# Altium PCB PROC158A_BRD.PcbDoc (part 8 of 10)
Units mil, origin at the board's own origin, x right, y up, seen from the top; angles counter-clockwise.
Board outline 3346.45 x 4921.26 mil, 8 copper layers (Top Layer, GND1, SIG1, PWR1, PWR2, SIG2, GND2, Bottom Layer), stack 54.534 mil thick; 718 components, 459 nets, 2307 pads, 1179 vias.
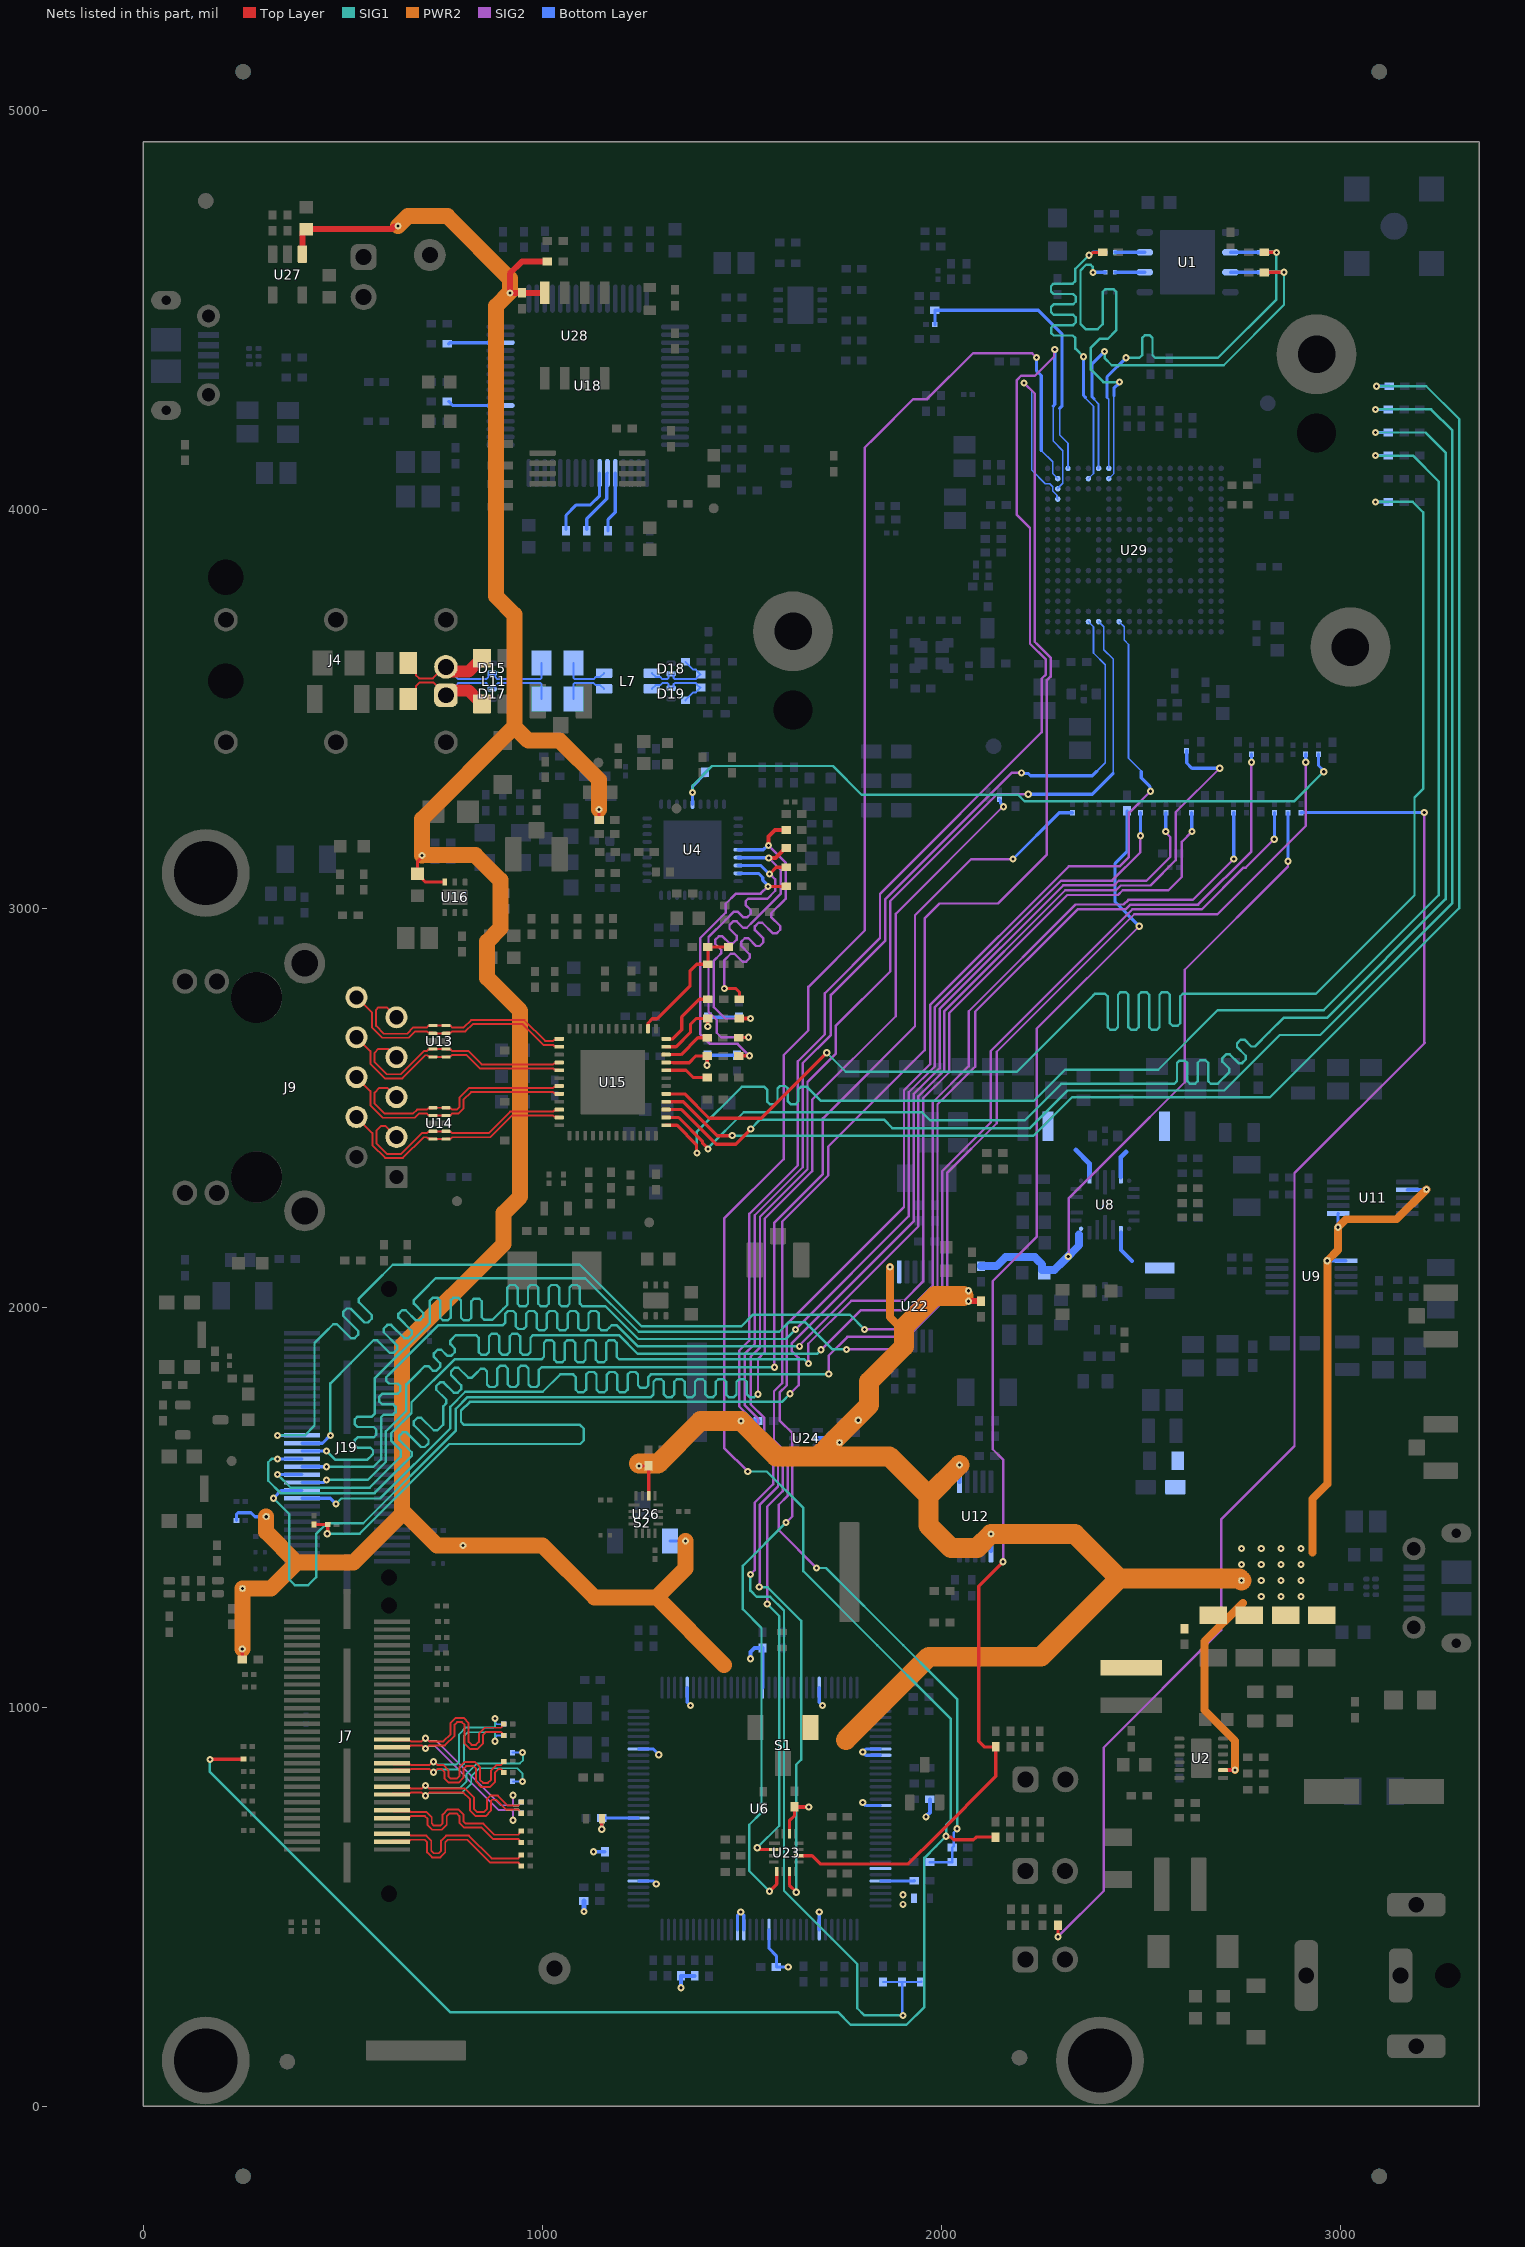
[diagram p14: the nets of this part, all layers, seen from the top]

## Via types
v1: diameter 18, hole 8, Top Layer to Bottom Layer, tented both sides, 1112 vias
v2: diameter 19.68, hole 7.87, Top Layer to Bottom Layer, 28 vias
v3: diameter 20, hole 10, Top Layer to Bottom Layer, tented both sides, 26 vias
v4: diameter 16/18/18/18/18/18/18/16 (per signal layer), hole 8, Top Layer to Bottom Layer, tented both sides, 13 vias

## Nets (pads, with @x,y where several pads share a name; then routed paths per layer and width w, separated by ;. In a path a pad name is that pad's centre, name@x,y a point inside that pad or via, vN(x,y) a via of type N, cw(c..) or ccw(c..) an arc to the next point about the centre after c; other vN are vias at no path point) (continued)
QSPI_D1: R39.1 R49.1 U29.U7 | length 1001.3
  Top Layer w8: R49.1@2808.26,4644.33 2808.36,4644.23 2838.37,4644.23 v1(2838.46,4644.14)
  SIG1 w6: v1(2462,4380) 2492.6,4380 2495.6,4380 2502.1,4386.5 2502.1,4429.71 2508.6,4436.21 2521.6,4436.21 2528.1,4429.71 2528.1,4386.5 2534.6,4380 2570,4380 2692,4380 2838.46,4526.46 v1(2838.46,4644.14)
  Bottom Layer w4: 2414.36,4281 2418.84,4276.52 U29.U7@2418.84,4102.97
  Bottom Layer w6.42: 2414.26,4281.11 2414.26,4282.37
  Bottom Layer w8: 2414.26,4281.11 2414.36,4281 ; 2414.26,4282.37 2414.26,4332.26 v1(2462,4380) ; R39.1@2818.26,4644.33 2818.36,4644.23 2838.37,4644.23 v1(2838.46,4644.14)
QSPI_D1_FLASH: R39.2 U1.2 | length 71.2
  Bottom Layer w8: U1.2@2723.49,4644.33 R39.2@2794.64,4644.33
QSPI_D2: R42.1 R43.1 U29.U6 | length 1020.6
  Top Layer w8: R43.1@2808.26,4594.03 2808.44,4594.21 2857.53,4594.21 v1(2857.71,4594.38)
  SIG1 w6: v1(2408.22,4396.17) 2408.22,4379.49 2426.19,4361.51 2706.51,4361.51 2857.71,4512.71 v1(2857.71,4594.38)
  Bottom Layer w4.5: 2381.66,4277.63 2381.66,4275.73 2393.25,4264.14 2393.25,4134.47 U29.U6@2393.25,4102.97
  Bottom Layer w8: 2381.66,4277.63 2376.29,4283.01 2376.29,4364.24 v1(2408.22,4396.17) ; R42.1@2818.26,4594.03 2818.44,4594.21 2857.53,4594.21 v1(2857.71,4594.38)
QSPI_D2_FLASH: R42.2 U1.3 | length 71.3
  Bottom Layer w8: U1.3@2723.49,4594.33 2723.64,4594.18 2794.49,4594.18 R42.2@2794.64,4594.03
QSPI_D3: R40.2 R41.1 U29.T5 | length 1004.9
  Top Layer w8: v1(2369,4637) 2371.71,4637 2378.87,4644.17 2403.24,4644.17 R41.1@2403.41,4644.33
  SIG1 w6: v1(2355.3,4382.67) 2335,4402.97 2335,4426.39 2335,4429.39 2328.5,4435.89 2280.76,4435.89 2274.26,4442.39 2274.26,4455.39 2280.76,4461.89 2329.28,4461.89 2335.78,4468.39 2335.78,4481.39 2329.28,4487.89 2280.48,4487.89 2273.98,4494.39 2273.98,4507.39 2280.48,4513.89 2329.28,4513.89 2335.78,4520.39 2335.78,4533.39 2329.28,4539.89 2280.48,4539.89 2273.98,4546.39 2273.98,4559.39 2280.48,4565.89 2328.5,4565.89 2335,4572.39 2335,4600.06 2335,4603 v1(2369,4637)
  Bottom Layer w4: 2359.99,4280.69 2359.99,4279.08 2380.42,4258.64 2380.42,4090.14 U29.T5@2367.66,4077.38
  Bottom Layer w8: v1(2355.3,4382.67) 2355.3,4285.69 2359.99,4281 ; v1@2369,4634.29 v1(2369,4637) 2371.71,4637 2379.04,4644.33 R40.2@2410.27,4644.33
QSPI_D3_FLASH: R40.1 U1.7 | length 74.9
  Bottom Layer w8: R40.1@2433.89,4644.33 U1.7@2508.8,4644.33
QSPI_SCLK: R44.2 U29.T7 | length 975.4
  SIG1 w6: v1(2379,4594) 2378.77,4594.23 2378.77,4607.23 2373.08,4612.92 2361.89,4612.92 2347.78,4598.81 2347.78,4464.52 2360.38,4451.92 2391.23,4451.92 2403.57,4464.26 2403.57,4545.33 2410.27,4552.02 2430.36,4552.02 2437,4545.38 2437,4448.44 2416,4427.44 2395.47,4427.44 2373.82,4405.79 2373.82,4350.49 2405.1,4319.21 v1(2445.85,4319.21)
  Bottom Layer w4: U29.T7@2418.84,4077.38 2431.6,4090.14 2431.6,4284.99
  Bottom Layer w8: v1(2379,4594) 2379.17,4594.17 2410.11,4594.17 R44.2@2410.27,4594.33 ; 2431.6,4284.99 2431.6,4303.76 2445.85,4318.01 v1(2445.85,4319.21)
QSPI_SCLK_FLASH: R44.1 U1.6 | length 74.9
  Bottom Layer w8: R44.1@2433.89,4594.33 U1.6@2508.8,4594.33
REF_FTDI: R157.2 U18.6 | length 134.4
  Bottom Layer w8: R157.2@765.07,4270.79 775.38,4260.47 U18.6@895.17,4260.47
REGOUT_3V3: C18.2 C22.2 C23.1 C25.1 C26.1 C29.1 C41.1 C42.2 C43.2 C47.2 C48.1 C50.1 C61.1 C76.2 C98.2 C133.1 C145.1 L1.1 L6.2 R11.1 R50.2 R124.2 R127.2 R134.2 R140.2 R155.2 R199.1 R200.1 R222.2 R243.2 R317.1 R416.2 R418.2 R503.1 R508.1 S1.1 S2.1 U2.8 U6.7 U6.8 U6.16 U6.26 U6.28 U6.39 U6.47 U6.51 U6.52 U6.69 U6.79 U6.90 U6.101 U6.113 U6.122 U9.6 U11.2 U11.6 U12.1 U12.6 U16.6 U22.6 U23.14 U24.5 U26.14 U27.1 U28.8 | length 14027.4
  Top Layer w8: v1(248.03,1145.67) 248.18,1145.52 248.18,1119.7 R418.2@248.33,1119.56 ; C48.1@687.02,3091.34 687.02,3118.92 698.58,3130.48 v1(698.58,3133.19) ; C48.1@688.62,3086.79 698.46,3076.95 698.46,3075.35 707.08,3066.73 U16.6@754.99,3066.73 ; v1(1141.69,3248.21) 1141.88,3248.03 1141.88,3222.47 R50.2@1142.06,3222.28 ; v1(1148.38,693.81) 1148.69,694.13 1148.69,720.31 C61.1@1149.01,720.62 ; v1(1242,1604) C18.2@1266.05,1604.02 1266.12,1603.95 1266.12,1529.74 U26.14@1266.18,1529.68 ; U23.14@1618.56,682.49 1618.56,715.04 1631.35,727.84 C98.2@1631.35,749.83
  Top Layer w10: C98.2@1631.35,749.83 v1(1667,749.83) ; U2.8@2705.09,842 v1(2735,842)
  Top Layer w15: U27.1@398.76,4642.54 398.76,4693.57 407.46,4702.27 C145.1@408.44,4702.27 621.36,4702.27 628.52,4709.43 637.43,4709.43 v1(638,4710) ; U28.8@1005.83,4543.13 1005.29,4542.59 C47.2@949.01,4542.59 v1(918.52,4542.59) 918.52,4591.26 948.21,4620.96 R416.2@1012.52,4620.96 ; v1(2066.93,2016.81) R199.1@2099,2016.81
  PWR2 w20: v1(1870.3,2102.69) 1870.3,1976.6 1894.95,1951.95 1905.95,1951.95 ; v1(2735,842) 2735,915.5 2658,992.5 2658,1164 2755,1261 ; 2928.91,1387 2928.91,1521.63 2966.18,1558.9 v1(2966.18,2118.23) 2993,2145.06 v1(2993,2201.81) 3013.19,2222 3139.65,2222 v1(3214.34,2296.69)
  PWR2 w40: v1(248.03,1145.67) 248.33,1145.97 v1(248.33,1297.35) 320.57,1297.35 385.03,1361.81 ; v1(308,1477) 308,1438.84 385.03,1361.81 ; v1(638,4710) 662.86,4734.86 762.14,4734.86 918.52,4578.48 918.52,4544.24 883.71,4509.43 883.71,3782.69 929.78,3736.61 929.78,3455.89 ; v1(1141.69,3248.21) 1141.69,3322.76 1043.3,3421.16 964.52,3421.16 929.78,3455.89 ; v1(1358,1416.13) 1358,1346.93 1285.85,1274.77 ; 1454.69,1105.93 1285.85,1274.77 ; 385.03,1361.81 526.09,1361.81 647.72,1483.44 647.72,1492.6 ; 647.72,1492.6 647.72,1905.23 902.57,2160.08 902.57,2237.49 943.9,2278.81 943.9,2744.1 861.26,2826.74 861.26,2917.6 894.66,2951.01 894.66,3071.34 832,3134 699.4,3134 v1(698.58,3133.19) 698.58,3224.69 929.78,3455.89 ; 647.72,1492.6 735.32,1405 v1(801,1405) 801.09,1405.09 1000,1405.09 1130.32,1274.77 1285.85,1274.77
  PWR2 w50: v1@1242,1609.85 1289.23,1609.85 1395.85,1716.46 v1(1497.18,1716.46) 1585.41,1628.24 1690.24,1628.24 ; 1760,918 1968,1126 2248.64,1126 2444.82,1322.18 ; v1(2044.72,1606.52) 1967.6,1529.4 ; 2054.22,2029.52 1983.52,2029.52 1905.95,1951.95 1905.95,1903 1818.5,1815.56 1818.5,1756.5 1690.24,1628.24 ; v1(2750.82,1317.28) 2745.92,1322.18 2444.82,1322.18 ; 1690.24,1628.24 1868.76,1628.24 1967.6,1529.4 ; 1967.6,1529.4 1967.6,1454.4 2023,1399 2089.17,1399 v1(2123.47,1433.29) 2333.71,1433.29 2444.82,1322.18
  Bottom Layer w8: R508.1@233.42,1467.61 233.42,1482.31 238.11,1487 270,1487 280,1477 v1(308,1477) ; v1(1128,637.67) R155.2@1156.34,637.67 ; v1(1141.69,3248.21) 1141.88,3248.03 1141.88,3222.47 R11.1@1142.06,3222.28 ; v1(1148.38,693.81) C42.2@1148.38,722.02 ; C42.2@1148.63,721.77 U6.79@1240.63,721.77 ; U6.69@1240.63,564.29 1277.34,564.29 v1(1285.22,556.42) ; U6.90@1240.63,895 1277.34,895 1291.55,880.79 v1(1291.55,880.41) ; S2.1@1319.33,1416.13 v1(1358,1416.13) ; U6.101@1362.68,1048.54 1362.68,1011.83 v1(1370.55,1003.96) ; U6.52@1488.66,442.24 1488.66,478.96 v1(1496.54,486.83) 1504.41,478.96 U6.51@1504.41,442.24 ; U6.113@1551.66,1048.54 C43.2@1551.66,1147.93 ; U6.47@1567.4,442.24 1567.4,395.41 1586.14,376.67 C50.1@1586.14,349.16 v1(1615.94,349.16) ; U6.39@1693.39,442.24 v1(1693.39,486.83) ; U6.122@1693.39,1048.54 1693.39,1011.83 v1(1701.26,1003.96) ; v1(1802.35,761.14) 1810.22,753.27 U6.16@1846.93,753.27 ; U6.28@1846.93,564.29 1847,564.35 1930.8,564.35 C76.2@1931.26,564.81 ; U6.8@1846.93,879.25 1810.22,879.25 v1(1802.35,887.13) 1810.22,895 U6.7@1846.93,895 ; v1(2966.18,2118.23) U9.6@3013.19,2118.23 ; v1(2993,2201.81) 2993,2236.16 U11.6@2993.39,2236.54 ; U11.2@3166.61,2295.6 3167.16,2296.14 3213.79,2296.14 v1(3214.34,2296.69)
  Bottom Layer w10: v1(248.33,1297.35) R503.1@278.9,1297.35 ; R243.2@753.28,1405.09 753.33,1405.05 800.95,1405.05 v1(801,1405) ; v1(1346.93,297) R124.2@1346.93,326.49 R127.2@1381.51,326.49 ; v1(1521,1121) 1521,1137.5 1531.43,1147.93 C43.2@1551.66,1147.93 ; v1(1961,725) 1961,727.16 1970.26,736.43 R140.2@1970.26,769.02 ; U12.6@2044.72,1564.42 v1(2044.72,1606.52) ; U12.1@2123.47,1391.19 v1(2123.47,1433.29)
  Bottom Layer w12: R134.2@1103.84,513.97 1104,513.81 v1(1104,488) ; v1@1497.18,1715.94 1497.71,1716.46 R222.2@1540.02,1716.46 ; U24.5@1689.61,1673.65 1709.42,1673.65 1721.27,1685.5 1743.75,1685.5 C133.1@1744.05,1685.81 v1(1744.05,1662.87) ; R317.1@1766.1,1718.43 1766.17,1718.5 1791.01,1718.5 v1(1791.08,1718.57)
  other v1: 1903,505.81 1903,529.81 2800.62,1277.28 2850.42,1277.28 2900.22,1277.28 2800.62,1317.28 2850.42,1317.28 2900.22,1317.28 2750.82,1357.28 2800.62,1357.28 2850.42,1357.28 2900.22,1357.28 2750.82,1397.28 2800.62,1397.28 2850.42,1397.28 2900.22,1397.28 2066.93,2043
RGMII_RD0: R173.1 R287.2 R325.2 U15.33 | length 232.9
  Top Layer w8: U15.33@1309.79,2614.76 1327.42,2614.76 ; 1327.89,2614.28 1367.54,2614.28 1384.57,2631.31 R325.2@1413.34,2631.31 1412.77,2630.74 1412.77,2608.54 v1(1412.19,2607.97)
  Bottom Layer w8: v1(1412.19,2607.97) 1412.7,2608.48 1412.7,2632.17 R173.1@1413.21,2632.68 R287.2@1487,2632.68
RGMII_RD1: R336.2 U15.34 | length 120.3
  Top Layer w8: U15.34@1309.79,2634.44 1347.28,2634.46 1389.42,2676.6 R336.2@1412.62,2676.6
RGMII_RD2: R286.1 R288.2 R338.2 U15.35 | length 267.5
  Top Layer w8: U15.35@1309.79,2654.13 1309.83,2654.16 1334.89,2654.16 1370.98,2690.25 1370.98,2710.51 1385.35,2724.89 R338.2@1414.06,2724.89 ; v1(1414.1,2704.62) R338.2@1414.08,2724.87
  Bottom Layer w8: v1(1414.1,2704.62) 1414.29,2704.81 1414.29,2727.67 R286.1@1414.48,2727.86 R288.2@1492.8,2727.86
RGMII_RD3: R339.2 U15.36 | length 164.6
  Top Layer w8: U15.36@1309.79,2673.81 1326.17,2673.81 1348.89,2696.53 1348.89,2728.82 1393.09,2773.01 1414.25,2773.01 R339.2@1414.33,2773.09
RGMII_TCLK: R98.2 U15.29 | length 3965.6
  Top Layer w8: U15.29@1309.79,2536.01 1356.25,2536.01 1417.23,2475.04 1548.04,2475.04 v1(1712,2639)
  SIG1 w6: v1(1712,2639) 1759.62,2591.38 2188.38,2591.38 2380.24,2783.24 2384,2787 2409.24,2787 2415.74,2780.5 2415.74,2703.25 2422.24,2696.75 2435.24,2696.75 2441.74,2703.25 2441.74,2784.4 2448.24,2790.9 2461.24,2790.9 2467.74,2784.4 2467.74,2703.25 2474.24,2696.75 2487.24,2696.75 2493.74,2703.25 2493.74,2784.4 2500.24,2790.9 2513.24,2790.9 2519.74,2784.4 2519.74,2703.25 2526.24,2696.75 2539.24,2696.75 2545.74,2703.25 2545.74,2784.4 2552.24,2790.9 2565.24,2790.9 2571.74,2784.4 2571.74,2713.18 2578.24,2706.68 2591.24,2706.68 2597.74,2713.18 2597.74,2780.5 2604.24,2787 2644.31,2787 2937.71,2787 3184.5,3033.79 3184.5,3278.5 3206,3300 3206,3993 3180,4019 v1(3087,4019)
  Bottom Layer w8: v1(3087,4019) R98.2@3119.26,4019
RGMII_TD0: R103.2 U15.28 | length 3757.7
  Top Layer w8: U15.28@1309.79,2516.33 1352.78,2516.33 1438.11,2431 1475.18,2431 v1(1475.64,2431.46)
  SIG1 w6: v1(1475.64,2431.46) 1476.1,2431 2229.96,2431 2326.46,2527.5 2822.62,2527.5 3296.45,3001.33 3296.45,4226.55 3214.16,4308.84 v1(3088.97,4308.84)
  Bottom Layer w8: v1(3088.97,4308.84) R103.2@3121.23,4308.84
RGMII_TD1: R105.2 U15.27 | length 3703.7
  Top Layer w8: U15.27@1309.79,2496.64 1348.5,2496.64 1435.14,2410 1484.5,2410 1521.98,2447.48 v1(1521.98,2448.18)
  SIG1 w6: v1(1521.98,2448.18) 1545.3,2471.5 1855.23,2471.5 1876.31,2450.43 2220.92,2450.43 2315,2544.5 2708.06,2544.5 2847.1,2683.54 2948.54,2683.54 3279.45,3014.45 3279.45,3164.43 3279.45,4197.55 3226.13,4250.87 v1(3087,4250.87)
  Bottom Layer w8: v1(3087,4250.87) R105.2@3119.26,4250.87
RGMII_TD2: R121.2 U15.26 | length 3948.5
  Top Layer w8: U15.26@1309.79,2476.96 1341.07,2476.96 1400.67,2417.36 1400.67,2413.37 1415,2399.05 v1(1415,2398)
  SIG1 w6: v1(1415,2398) 1415,2400.7 1504.44,2490.13 1951.12,2490.13 1971.25,2470 2208.5,2470 2300,2561.5 2579.97,2561.5 2582.97,2561.5 2589.47,2568 2589.47,2613.06 2595.97,2619.56 2608.97,2619.56 2615.47,2613.06 2615.47,2568 2621.97,2561.5 2634.97,2561.5 2641.47,2568 2641.47,2613.97 2647.97,2620.47 2660.97,2620.47 2667.47,2613.97 2667.47,2568 2673.97,2561.5 2691.33,2561.5 2692.74,2562.91 2718.18,2588.34 2720.3,2590.47 2720.3,2599.66 2703.21,2616.74 2703.21,2625.94 2712.4,2635.13 2721.6,2635.13 2743.53,2613.2 2752.72,2613.2 2761.91,2622.39 2761.91,2631.58 2739.98,2653.51 2739.98,2662.71 2749.17,2671.9 2758.37,2671.9 2775.45,2654.81 2784.64,2654.81 2820.59,2690.76 2856.33,2726.5 2965,2726.5 3262.45,3023.95 3262.45,4142.55 3212.09,4192.91 v1(3087,4192.91)
  Bottom Layer w8: v1(3087,4192.91) R121.2@3119.26,4192.91
RGMII_TD3: R122.2 U15.25 | length 3704.5
  Top Layer w8: U15.25@1309.79,2457.27 1337.4,2457.27 1385.67,2409 1385.67,2389.33 v1(1387,2388)
  SIG1 w6: v1(1387,2388) 1387,2441.5 1499.18,2553.68 1527.34,2553.68 1556.34,2553.68 1562.84,2547.18 1562.84,2516.94 1569.34,2510.44 1582.34,2510.44 1588.84,2516.94 1588.84,2549.44 1595.34,2555.94 1608.34,2555.94 1614.84,2549.44 1614.84,2516.94 1621.34,2510.44 1634.34,2510.44 1640.84,2516.94 1640.84,2547.18 1647.34,2553.68 1657.13,2553.68 1662.92,2553.68 1698.1,2518.5 2230.9,2518.5 2309.11,2596.71 2542.57,2596.71 2691.37,2745.5 2957,2745.5 3245.45,3033.95 3245.45,4069.87 3180.39,4134.94 v1(3087,4134.94)
  Bottom Layer w8: v1(3087,4134.94) R122.2@3119.26,4134.94
RST_FTDI: R163.2 U18.14 | length 131.3
  Bottom Layer w8: R163.2@765.07,4415.03 767.99,4417.95 U18.14@895.17,4417.95
RX_CLK: R290.2 U15.32 | length 110.7
  Top Layer w8: U15.32@1309.79,2595.07 1359.53,2595.07 1377.58,2577.02 R290.2@1413.04,2577.02
RX_CTRL: R195.2 R211.1 R289.2 U15.38 | length 341.8
  Top Layer w8: U15.38@1264.51,2699.4 1264.51,2713.47 1275.25,2724.21 1287.3,2724.21 1324.95,2761.86 1324.95,2762.1 1369.9,2807.06 1369.9,2844.66 1386.05,2860.81 R195.2@1414.32,2860.81 R211.1@1414.33,2903.81 R289.2@1466,2903.81
RX_D0: R237.2 R255.1 U4.26 | length 784.6
  Top Layer w8: R237.2@1492.08,2631.31 1492.14,2631.37 v1(1518.69,2631.37) ; v1(1564.68,3055.84) 1564.79,3055.95 1606.29,3055.95 R255.1@1606.4,3056.06
  SIG2 w6: v1(1518.69,2631.37) 1488.85,2661.21 1419.56,2661.21 1394.93,2685.84 1394.93,2925.75 1459.31,2990.13 1459.31,3012.41 1484.52,3037.62 1546.46,3037.62 v1(1564.68,3055.84)
  Bottom Layer w8: U4.26@1490.38,3088.51 1541.28,3088.51 1551.71,3078.07 1551.71,3071.5 1564.68,3058.54 v1(1564.68,3055.84)
RX_D1: R238.2 R256.1 U4.25 | length 802.1
  Top Layer w8: R238.2@1491.36,2676.6 1491.97,2677.21 1515.39,2677.21 v1(1516,2677.81) ; v1(1568.7,3086.55) 1586.1,3103.94 R256.1@1606.4,3103.94
  SIG2 w6: v1(1516,2677.81) 1447.69,2677.81 1436.43,2689.07 1436.43,2721.14 1415.97,2741.61 1415.97,2928.84 1459.18,2972.05 1479.69,2992.55 1488.88,2992.55 1503.38,2978.06 1512.57,2978.06 1521.76,2987.25 1521.76,2996.44 1508.83,3009.37 1508.83,3018.56 1515.33,3025.06 1520.54,3025.06 1563.37,3025.06 1583.15,3044.83 1583.15,3073.31 1569.91,3086.55 v1(1568.7,3086.55)
  Bottom Layer w8: U4.25@1490.38,3108.2 1547.05,3108.2 v1(1568.7,3086.55)
RX_D2: R239.2 R257.1 U4.24 | length 833.2
  Top Layer w10: R239.2@1492.8,2724.89 1492.84,2724.85 1520.96,2724.85 v1(1521,2724.81) ; v1(1566.7,3126.89) 1583.29,3126.89 1608.37,3151.97 R257.1@1610.34,3151.97
  SIG2 w6: v1(1521,2724.81) 1457.75,2724.81 1429.58,2752.98 1429.58,2870.08 1445.47,2885.96 1447.59,2888.08 1447.59,2897.28 1432.57,2912.3 1432.57,2921.49 1441.76,2930.69 1450.95,2930.69 1468.22,2913.42 1477.41,2913.42 1486.6,2922.61 1486.6,2931.8 1468.53,2949.88 1468.53,2959.07 1477.72,2968.26 1486.91,2968.26 1502.74,2952.43 1511.94,2952.43 1528.41,2968.9 1597.18,3037.67 1597.18,3096.41 v1(1566.7,3126.89)
  Bottom Layer w8: U4.24@1490.38,3127.88 1490.87,3127.39 1566.21,3127.39 v1(1566.7,3126.89)
RX_D3: R16.1 R240.2 U4.23 | length 871.1
  Top Layer w8: v1(1455.65,2800.13) 1484.49,2800.13 1493.56,2791.05 R240.2@1493.56,2773.59
  Top Layer w10: v1(1566.5,3158.03) 1566.5,3180.27 1583.04,3196.81 R16.1@1610.34,3196.81
  SIG2 w6: v1(1455.65,2800.13) 1455.65,2862.32 1455.65,2871.28 1471.67,2887.31 1480.86,2887.31 1501.02,2867.15 1510.21,2867.15 1519.4,2876.34 1519.4,2885.54 1497.55,2907.39 1497.55,2916.58 1506.74,2925.78 1515.94,2925.78 1535.11,2906.6 1544.31,2906.6 1553.5,2915.79 1553.5,2924.98 1532.07,2946.41 1532.07,2955.6 1541.27,2964.79 1550.46,2964.79 1577.26,2937.99 1586.45,2937.99 1595.65,2947.18 1595.65,2956.37 1572.79,2979.23 1572.79,2988.42 1604.97,3020.61 1609.18,3024.82 1609.18,3115.35 v1(1566.5,3158.03)
  Bottom Layer w8: U4.23@1490.38,3147.57 1553.42,3147.57 1563.88,3158.03 v1(1566.5,3158.03)
SOP0_FTDI: R171.1 U18.55 | length 196.5
  Bottom Layer w8: R171.1@1058.91,3950.19 1058.91,3985.34 1085.16,4011.58 1120.24,4011.58 1143.2,4034.54 U18.55@1143.2,4091.18
SOP0_TDO: R310.1 R386.1 U23.10 | length 3271.9
  Top Layer w8: U23.10@1642.18,627.37 1675.44,627.37 1695.81,607 1916.35,607 1986,676.65 2135.56,826.21 R310.1@2135.56,900.17 2106.83,900.17 2092.72,914.28 2092.72,1302.72 v1(2154,1364)
  SIG2 w6: v1(2154,1364) 2154,1619.76 2128,1645.76 2128,2067.46 2238,2177.46 2238,2699.1 v1(2495.08,2956.18)
  Bottom Layer w8: R386.1@2464,3245.02 2464.5,3244.52 2464.5,3143.5 2434.5,3113.5 2434.5,3016.75 v1(2495.08,2956.18)
SOP1_FTDI: R170.1 U18.54 | length 162.4
  Bottom Layer w8: R170.1@1111.12,3950.19 1111.12,3976.45 1161.12,4026.45 1161.12,4089.42 U18.54@1162.89,4091.18
SOP1_MSS_SPIB_CS2: R305.1 R324.1 U29.T2 | length 7516.5
  Top Layer w8: v1(167,869) 167.41,869.41 250.57,869.41 R324.1@250.98,869.81 ; v1(2011.22,676.41) 2013.13,674.5 2023.01,674.5 2029.7,667.81 2079.81,667.81 2086.32,674.32 2133.84,674.32 R305.1@2134.62,673.54
  SIG1 w6: v1(167,869) 167,837.46 768.64,235.81 1740.26,235.81 1772.07,204 1911.93,204 1956.87,248.94 1956.87,271 1956.87,622.06 1986,651.19 v1(2011.22,676.41) 2011.22,704.65 2022.51,715.95 2022.51,971.28 1986,1007.8 1838.8,1155 1653.52,1340.28 1653.52,1498.48 1562,1590 v1(1514.49,1590)
  SIG2 w6: v1(1514.49,1590) 1455.18,1649.31 1455.18,2223.5 1604,2372.32 1604,2632.99 1666.33,2695.32 1666.33,2804.24 1807.5,2945.41 1807.5,4155 1834.5,4182 ; 1834.52,4181.98 1929,4276.46 1963.66,4276.46 2078.67,4391.47 2226.62,4391.47 v1(2237.29,4380.8)
  Bottom Layer w4: 2249.81,4147.65 2278.05,4119.41 2278.05,4108.27 ; 2278.05,4097.67 2278.05,4090.23 U29.T2@2290.89,4077.38 ; 2278.06,4097.69 2278.06,4108.26
  Bottom Layer w8: v1(2237.29,4380.8) 2237.29,4347.92 2249.48,4335.73 2249.48,4147.98 2249.81,4147.65
SOP2_FTDI: R169.1 U18.53 | length 152.4
  Bottom Layer w8: R169.1@1164.49,3946.25 1164.49,3975.2 1182.57,3993.28 U18.53@1182.57,4091.18
SOP2_PMIC_CLK: R218.2 R299.1 | length 3537
  Top Layer w8: v1(2291.63,424.85) R299.1@2291.63,453.72
  SIG2 w6: v1(2291.63,424.85) 2406,539.22 2406,898.6 2700.13,1192.74 2700.13,1469.71 2884,1653.58 2884,2337.58 3210.5,2664.08 3209.07,2665.51 v1(3209.07,3240.92)
  Bottom Layer w8: R218.2@2899.94,3240.92 v1(3209.07,3240.92) 3209.8,3240.92 v1@3210.16,3240.56 ; R218.2@2900.69,3240.22 R218.2@2901.03,3240.56
SOP3_MSS_UARTB_TX: R136.1 R301.1 R303.2 U29.P2 | length 4721.6
  SIG1 w6: v1(1686.77,1348.39) 1710.5,1348.39 1903.89,1155 1986,1072.89 2038.8,1020.09 v1(2038.8,694.99)
  SIG2 w6: v1(1686.77,1348.39) 1592,1443.16 1592,1506.97 1614,1528.97 1614,1634.36 1580,1668.36 1580,1791 1600.29,1811.29 1600.29,2215.87 1716,2331.58 1716,2404 1957.38,2645.38 1957.38,2975.49 1994.89,3013 2141.17,3013 2262.9,3134.73 2262.9,3571.3 2273.05,3581.45 2273.05,3628.94 2239.97,3662.03 2239.48,3662.51 2239.05,3662.94 2238.73,3663.27 2233.23,3668.77 2233.23,4290.34 v1(2206.67,4316.89)
  Bottom Layer w4: v1(2206.67,4316.89) 2226.16,4297.4 2226.16,4098.19 2259.73,4064.62 2270.52,4064.62 2278.13,4057.01 2278.13,4046.51 2289.03,4035.61 2289.03,4028.06 U29.P2@2290.89,4026.2
  Bottom Layer w6: R136.1@1969.68,611.54 R303.2@2026.47,611.54 R301.1@2026.47,647.92 2030.21,651.66 2030.21,685.48 2038.8,694.07 v1(2038.8,694.99)
SOP4_MSS_UARTA_TX: R128.1 R309.1 R312.2 U29.R2 | length 5421.1
  SIG1 w6: v1(1521,1332) 1521,1291.73 1536.66,1276.08 1570.62,1276.08 1605,1241.69 1605,1155 1605,539.78 1788.4,356.39 1788.4,271 1788.4,245.7 1806.32,227.77 1902.39,227.77 v1(1902.85,227.3)
  SIG2 w6: v1(1521,1332) 1532,1343 1532,1512.54 1578,1558.54 1578,1616 1525.89,1668.11 1525.89,1719.94 1492.89,1752.94 1492.89,1893.01 1518,1918.12 1518,2235.4 1640,2357.4 1640,2618 1707.12,2685.12 1707.12,2787.69 1845.63,2926.2 1845.63,3037.13 2250.9,3442.4 2250.9,3576.27 2261.05,3586.42 2261.05,3623.97 2221.23,3663.8 2221.23,3953.77 2188.5,3986.5 2188.5,4324.17 2199.22,4334.89 2233.8,4334.89 2281.36,4382.45 2281.36,4398.57 v1(2283.24,4400.45)
  Bottom Layer w4: 2279.28,4259 2279.28,4171.32 2303.65,4146.95 2303.65,4065.7 2290.89,4052.94 U29.R2@2290.89,4051.79
  Bottom Layer w6: R128.1@1853.15,311.19 R309.1@1901,311.19 ; v1(1902.85,227.3) 1901.72,228.44 1901.72,271 1901.72,310.47 R309.1@1901,311.19 ; R312.2@1949.3,312.49 R312.2@1948,311.19 R309.1@1901,311.19
  Bottom Layer w8: 2279.28,4259 2283.24,4262.96 v1(2283.24,4400.45)
SPIB_CS1/SPI_HOST_IRQ: R18.2 R55.2 U29.U3 | length 726.8
  Bottom Layer w4: 2295.58,4253.15 2295.58,4186.64 2316.48,4165.74 2316.48,4134.47 2316.48,4134.18 U29.U3@2316.48,4102.97
  Bottom Layer w8: R18.2@1983,4463 R55.2@1983,4499 2242.43,4499 2301.24,4440.2 2301.24,4258.81 2295.58,4253.15
STRP_1: R78.1 R253.1 U4.14 | length 1823.8
  SIG1 w6: v1(1376.2,3291.35) 1376.89,3292.04 1376.89,3309.35 1424.98,3357.44 1727.63,3357.44 1799.87,3285.2 2164.8,3285.2 2191.83,3285.2 2197.03,3280 2208.18,3268.85 2882.85,3268.85 v1(2957,3343)
  Bottom Layer w8: U4.14@1376.2,3261.74 v1(1376.2,3291.35) 1376.2,3306.53 R253.1@1407.02,3337.35 ; R78.1@2944,3387.3 2944,3358.7 2957,3345.71 v1(2957,3343)
SW_B1: L9.1 U8.24 | length 68.3
  Bottom Layer w12: U8.24@2448.85,2328 2448.85,2377.66 2462,2390.81
SW_B2: L8.1 U8.20 | length 81.9
  Bottom Layer w12: 2336,2395.81 2370.11,2361.7 U8.20@2370.11,2328
SW_B3: L2.1 U8.8 | length 82.7
  Bottom Layer w10: U8.8@2448.85,2188.63 2448.85,2145.18 2476.59,2117.45
SYNC_CLK: C171.2 R104.2 R106.1 U8.13 | length 1669.1
  SIG2 w6: v1(2317,2129) 2318,2130 2318,2274.33 2436.67,2393 2608.92,2565.25 2608.92,2846.98 2867.74,3105.8 2867.74,3118.74 v1(2868,3119)
  Bottom Layer w8: R104.2@2867.31,3240.22 2867.66,3239.88 2867.66,3119.34 v1(2868,3119)
  Bottom Layer w20: R106.1@2099,2104.75 2137.88,2104.75 2160.13,2127 2226,2127 2233.69,2127 2241.69,2119 2251.81,2108.87 2251.81,2094.73 2282.15,2094.73 2306.42,2119 2344.49,2157.07 2344.49,2184.22
TCK: U23.2 U29.B6 | length 3729.4
  Top Layer w8: v1(1538.13,647.79) 1540.84,647.79 1545.51,643.12 U23.2@1579.19,643.12
  SIG1 w6: v1(1538.13,647.79) 1593,702.66 1593,1155 1593,1228.24 v1(1563.16,1258.08)
  SIG2 w6: v1(1563.16,1258.08) 1563.16,1502.08 1602,1540.92 1602,1625.94 1556,1671.94 1556,1723.77 1521.94,1757.84 1521.94,1877.81 1545,1900.87 1545,2228.46 1664,2347.46 1664,2565.54 1734.44,2635.98 1734.44,2706.22 1871.25,2843.03 1871.25,3019.25 2138.85,3286.85 v1(2216.88,3286.85)
  Bottom Layer w4: U29.B6@2393.25,3719.11 2406.01,3706.35 2406.01,3648.99 2429.59,3625.41 2429.59,3345.99 2429.63,3345.96 2429.63,3339.18
  Bottom Layer w8: v1(2216.88,3286.85) 2377.3,3286.85 2429.63,3339.18
TD_1_N: J9.10 U13.2 U13.9 U15.2 | length 613.1
  Top Layer w4.8: J9.10@534.18,2777.93 573.05,2739.06 573.05,2702.21 598.65,2676.61 665.08,2676.61 681.01,2692.54 710.31,2692.54 713.52,2689.33 724.1,2689.33 U13.2@725.63,2687.79 U13.9@758.51,2687.79 760.04,2689.33 770.62,2689.33 773.83,2692.54 807.12,2692.54 825.52,2710.94 950.42,2710.94 1002.48,2658.87 1026.85,2658.87 1029.26,2656.45 1039.75,2656.45 U15.2@1042.07,2654.13
TD_1_P: J9.9 U13.1 U13.10 U15.1 | length 612.6
  Top Layer w4.8: J9.9@634.18,2727.93 609.4,2752.71 589.21,2752.71 583.25,2746.75 583.25,2706.44 602.88,2686.81 660.86,2686.81 676.79,2702.74 710.31,2702.74 713.52,2705.94 724.1,2705.94 U13.1@725.63,2707.48 U13.10@758.51,2707.48 760.04,2705.94 770.62,2705.94 773.83,2702.74 802.9,2702.74 821.3,2721.14 954.64,2721.14 1006.71,2669.07 1026.85,2669.07 1029.26,2671.49 1039.75,2671.49 U15.1@1042.07,2673.81
TD_2_N: J9.8 U13.5 U13.6 U15.5 | length 612.6
  Top Layer w4.8: J9.8@534.18,2677.93 569.08,2643.03 569.08,2611.37 605.44,2575.01 649.2,2575.01 707,2632.82 710.98,2632.82 713.52,2630.27 724.1,2630.27 U13.5@725.63,2628.74 U13.6@758.51,2628.74 760.04,2630.27 770.62,2630.27 773.83,2633.48 809.66,2633.48 843.28,2599.85 939.59,2599.85 939.64,2599.81 1026.85,2599.81 1029.26,2597.39 1039.75,2597.39 U15.5@1042.07,2595.07
TD_2_P: J9.7 U13.4 U13.7 U15.4 | length 610.4
  Top Layer w4.8: J9.7@634.18,2627.93 613.39,2648.72 589.21,2648.72 579.28,2638.79 579.28,2615.6 609.66,2585.21 644.97,2585.21 698.95,2639.18 ; 699.02,2639.11 698.95,2639.18 ; U15.4@1042.07,2614.76 1039.75,2612.43 1029.26,2612.43 1026.85,2610.01 943.86,2610.01 943.82,2610.05 847.51,2610.05 813.88,2643.68 773.83,2643.68 770.62,2646.89 760.04,2646.89 U13.7@758.51,2648.42 U13.4@725.63,2648.42 724.1,2646.89 713.52,2646.89 709.65,2643.02 702.78,2643.02 698.95,2639.18
TD_3_N: J9.6 U14.2 U14.9 U15.8 | length 616.7
  Top Layer w4.8: J9.6@534.18,2577.93 569.08,2543.03 569.08,2507.48 600.28,2476.27 679.83,2476.27 690.02,2486.46 710.31,2486.46 713.52,2483.26 724.1,2483.26 U14.2@725.63,2481.72 U14.9@758.51,2481.72 760.04,2483.26 770.62,2483.26 773.83,2486.46 789.46,2486.46 801.98,2498.98 801.98,2521.55 821.18,2540.76 1026.85,2540.76 1029.26,2538.34 1039.75,2538.34 U15.8@1042.07,2536.01
TD_3_P: J9.5 U14.1 U14.10 U15.7 | length 616
  Top Layer w4.8: J9.5@634.18,2527.93 611.25,2550.86 590.65,2550.86 579.28,2539.48 579.28,2511.7 604.51,2486.47 675.61,2486.47 685.8,2496.66 710.31,2496.66 713.52,2499.87 724.1,2499.87 U14.1@725.63,2501.4 U14.10@758.51,2501.4 760.04,2499.87 770.62,2499.87 773.83,2496.66 785.24,2496.66 791.78,2503.2 791.78,2525.78 816.96,2550.96 1026.85,2550.96 1029.26,2553.38 1039.75,2553.38 U15.7@1042.07,2555.7
TD_4_N: J9.4 U14.5 U14.6 U15.11 | length 618.1
  Top Layer w4.8: J9.4@534.18,2477.93 574.24,2437.87 574.24,2407.23 605.87,2375.59 650.24,2375.59 702.06,2427.41 710.31,2427.41 713.52,2424.2 724.1,2424.2 U14.5@725.63,2422.66 U14.6@758.51,2422.66 760.04,2424.2 770.62,2424.2 773.83,2427.41 869.11,2427.41 923.31,2481.6 981.72,2481.6 981.82,2481.7 1026.85,2481.7 1029.26,2479.28 1039.75,2479.28 U15.11@1042.07,2476.96
TD_4_P: J9.3 U14.4 U14.7 U15.10 | length 617.5
  Top Layer w4.8: J9.3@634.18,2427.93 606.1,2456.01 595.64,2456.01 584.44,2444.81 584.44,2411.45 610.1,2385.79 646.02,2385.79 697.84,2437.61 710.31,2437.61 713.52,2440.81 724.1,2440.81 U14.4@725.63,2442.35 U14.7@758.51,2442.35 760.04,2440.81 770.62,2440.81 773.83,2437.61 864.89,2437.61 919.08,2491.8 977.49,2491.8 977.59,2491.9 1026.85,2491.9 1029.26,2494.32 1039.75,2494.32 U15.10@1042.07,2496.64
TDI: U23.5 U29.B8 | length 3846.9
  Top Layer w8: v1(1569,538.81) 1569.29,538.81 1587.06,556.58 U23.5@1587.06,588
  SIG1 w6: v1(1569,538.81) 1518.13,589.68 1518.13,705.08 1548.69,735.64 1548.69,1155 1548.69,1198.31 1501.69,1245.31 1501.69,1353.69 v1(1610,1462)
  SIG2 w6: v1(1610,1462) 1626,1478 1626,1685.91 1594,1717.91 1594,1788.03 1612.29,1806.32 1612.29,1959.29 1905.69,2252.69 1905.69,2545.02 1971,2610.33 1971,2758.57 2318.33,3105.9 2445.47,3105.9 2469,3129.43 2469,3240 v1(2523,3294)
  Bottom Layer w4: U29.B8@2444.44,3719.11 2457.27,3706.28 2457.27,3672.93 2468.17,3662.03 2468.17,3376.88 2500.14,3344.91 2500.14,3344
  Bottom Layer w8: 2500.14,3344 2500.14,3327.86 2521.57,3306.43 2521.57,3295.43 v1(2523,3294)
TMS: U23.7 U29.B5 | length 3876.8
  Top Layer w8: U23.7@1618.56,588 1618.56,554.09 1635.98,536.67 v1(1635.98,536.15)
  SIG1 w6: v1(1543.24,1300.46) 1543.78,1299.92 1564.24,1299.92 1648,1216.15 1648,1155 1648,868 1635.98,855.98 v1(1635.98,536.15)
  SIG2 w6: v1(1543.24,1300.46) 1544,1301.22 1544,1506.53 1590,1552.53 1590,1620.97 1540.29,1670.68 1540.29,1722.51 1506.43,1756.38 1506.43,1884.44 1531.7,1909.71 1531.7,2232.13 1652,2352.43 1652,2613.03 1722.44,2683.47 1722.44,2784.03 1858.97,2920.56 1858.97,3023.94 2175.33,3340.3 v1(2200,3340.3)
  Bottom Layer w4: U29.B5@2367.66,3719.11 2380.42,3706.35 2380.42,3640.58 2409.93,3611.07 2409.93,3365.59 2388.34,3344
  Bottom Layer w8: v1(2200,3340.3) 2201.91,3338.39 2217.61,3338.39 2223,3333 2377.34,3333 2388.34,3344
TRACE_CLK: R72.1 R216.2 R226.1 | length 3995.3
  Top Layer w8: R72.1@427.98,1457.52 440.56,1457.52 440.66,1457.42 R226.1@461.96,1457.42 461.96,1435.33 v1(460.97,1434.35)
  SIG1 w6: v1(460.97,1434.35) 541.93,1434.35 766.58,1659 1094.62,1659 1103.57,1667.95 1103.57,1697.61 1094.18,1707 803.78,1707 796.01,1714.76 796.01,1742.52 818.1,1764.61 1599.96,1764.61 v1(1620.14,1784.79)
  SIG2 w6: v1(1620.14,1784.79) 1641.59,1806.24 1641.59,1874.67 1624.29,1891.97 1624.29,1911.05 1929.69,2216.45 1929.69,2535.07 1995,2600.39 1995,2748.63 2304.75,3058.37 2431.89,3058.37 2443.69,3070.18 2513.18,3070.18 2572.85,3129.85 2572.85,3179.7 2561.19,3191.36 v1(2561.19,3193.49)
  Bottom Layer w8: v1(2561.19,3193.49) 2561.54,3193.85 2561.54,3239.87 R216.2@2561.9,3240.22
TRACE_CTL: J19.17 R220.2 | length 3855.7
  SIG1 w6: v1(482.54,1508.92) 496,1522.38 593.19,1522.38 769,1698.2 769,1752 806.75,1789.75 1000.91,1789.75 1044.44,1833.27 1047.79,1833.27 1076.79,1833.27 1083.29,1826.77 1083.29,1795.11 1089.79,1788.61 1102.79,1788.61 1109.29,1795.11 1109.29,1832.89 1115.79,1839.39 1128.79,1839.39 1135.29,1832.89 1135.29,1795.11 1141.79,1788.61 1154.79,1788.61 1161.29,1795.11 1161.29,1832.89 1167.79,1839.39 1180.79,1839.39 1187.29,1832.89 1187.29,1795.11 1193.79,1788.61 1206.79,1788.61 1213.29,1795.11 1213.29,1832.89 1219.79,1839.39 1232.79,1839.39 1239.29,1832.89 1239.29,1806 1245.79,1799.5 1258.79,1799.5 1265.29,1806 1265.29,1826.77 1271.79,1833.27 1298.24,1833.27 1716.4,1833.27 v1(1717.29,1834.17)
  SIG2 w6: v1(1717.29,1834.17) 1717.29,1880.75 1763.77,1927.23 1898.2,1927.23 2001.69,2030.72 2001.69,2342.96 2123,2464.28 2123,2635.88 2123.07,2635.96 2123.07,2643.57 2477.68,2998.18 2651.72,2998.18 2756.54,3103 2762,3103 v1(2833,3174)
  Bottom Layer w8: J19.17@397.49,1523.18 468.28,1523.18 v1(482.54,1508.92) ; v1(2833,3174) 2833.47,3174.47 2833.47,3239.75 R220.2@2833.94,3240.22
TRACE_DATA0: J19.19 R227.1 | length 3893.1
  SIG1 w6: v1(326.24,1523.18) 365.66,1483.76 365.66,1319.55 379.64,1305.57 413.36,1305.57 433,1325.21 433,1433.49 460.14,1460.63 551.24,1460.63 783.15,1692.54 783.15,1747.15 812.61,1776.61 1268.64,1776.61 1271.64,1776.61 1278.14,1783.11 1278.14,1814.77 1284.64,1821.27 1297.64,1821.27 1304.14,1814.77 1304.14,1783.11 1310.64,1776.61 1323.64,1776.61 1330.14,1783.11 1330.14,1814.77 1336.64,1821.27 1349.64,1821.27 1356.14,1814.77 1356.14,1783.11 1362.64,1776.61 1375.64,1776.61 1382.14,1783.11 1382.14,1814.77 1388.64,1821.27 1401.64,1821.27 1408.14,1814.77 1408.14,1783.11 1414.64,1776.61 1427.64,1776.61 1434.14,1783.11 1434.14,1814.77 1440.64,1821.27 1453.64,1821.27 1460.14,1814.77 1460.14,1783.11 1466.64,1776.61 1479.64,1776.61 1486.14,1783.11 1486.14,1814.77 1492.64,1821.27 1505.64,1821.27 1512.14,1814.77 1512.14,1783.11 1518.64,1776.61 1530.42,1776.61 1537.32,1783.51 1537.65,1783.51 v1(1539.94,1783.51)
  SIG2 w6: v1(1539.94,1783.51) 1539.94,1872.06 1557,1889.12 1557,2223.49 1676,2342.49 1676,2521.68 1885,2730.68 1885,2986.99 2153.21,3255.2 v1(2155.17,3255.2)
  Bottom Layer w8: v1(326.24,1523.18) 345.93,1542.86 J19.19@397.49,1542.86 ; R227.1@2145,3273.17 2147.3,3270.87 2147.3,3264.89 2155.17,3257.02 v1(2155.17,3255.2)
TRACE_DATA1: J19.21 R231.1 | length 3925.3
  SIG1 w6: v1(459.31,1569.14) 562.45,1569.14 607.76,1614.45 607.76,1691 659.2,1742.44 659.2,1808.2 684.49,1833.49 704.99,1853.99 714.19,1853.99 725.3,1842.88 734.49,1842.88 743.69,1852.07 743.69,1861.26 728.13,1876.82 728.13,1886.01 737.32,1895.21 746.51,1895.21 762.07,1879.65 771.26,1879.65 780.46,1888.84 780.46,1898.03 769.34,1909.15 769.34,1918.34 782.8,1931.8 798.03,1931.8 804.54,1931.8 833.54,1931.8 840.04,1925.3 840.04,1889.5 846.54,1883 859.54,1883 866.04,1889.5 866.04,1928.62 872.54,1935.12 885.54,1935.12 892.04,1928.62 892.04,1889.5 898.54,1883 911.54,1883 918.04,1889.5 918.04,1928.62 924.54,1935.12 937.54,1935.12 944.04,1928.62 944.04,1889.5 950.54,1883 963.54,1883 970.04,1889.5 970.04,1925.3 976.54,1931.8 1014.37,1931.8 1191.87,1931.8 1238.89,1884.77 1687.91,1884.77 v1(1698.03,1894.88)
  SIG2 w6: v1(1698.03,1894.88) 1796.76,1993.61 1915.01,1993.61 1977.69,2056.29 1977.69,2515.19 2068,2605.51 2068,2743 2335.37,3010.37 2455.93,3010.37 2467.74,3022.18 2629.05,3022.18 v1(2731.64,3124.77)
  Bottom Layer w8: J19.21@397.49,1562.55 452.21,1562.55 v1@458.81,1569.14 ; R231.1@2731.39,3240.22 2731.52,3240.1 2731.52,3124.9 v1(2731.64,3124.77)
TRACE_DATA2: J19.23 R235.1 | length 3992.4
  SIG1 w6: v1(336.62,1582.23) 369.46,1549.39 567.16,1549.39 644.73,1626.96 644.73,1643.81 621,1667.54 621,1686 672.02,1737.02 672.02,1763.43 779.59,1871 994.37,1871 997.37,1871 1003.87,1877.5 1003.87,1912.75 1010.37,1919.25 1023.37,1919.25 1029.87,1912.75 1029.87,1869.89 1036.37,1863.39 1049.37,1863.39 1055.87,1869.89 1055.87,1912.75 1062.37,1919.25 1075.37,1919.25 1081.87,1912.75 1081.87,1869.89 1088.37,1863.39 1101.37,1863.39 1107.87,1869.89 1107.87,1912.75 1114.37,1919.25 1127.37,1919.25 1133.87,1912.75 1133.87,1869.89 1140.37,1863.39 1153.37,1863.39 1159.87,1869.89 1159.87,1912.75 1166.37,1919.25 1179.37,1919.25 1185.87,1912.75 1185.87,1877.5 1192.37,1871 1237.32,1871 1656.31,1871 v1(1666.33,1860.98)
  SIG2 w6: v1(1666.33,1860.98) 1666,1861.31 1666,1910.2 1773.42,2017.61 1905.07,2017.61 1953.69,2066.23 1953.69,2525.13 2019,2590.45 2019,2738.68 2314.69,3034.37 2441.83,3034.37 2453.63,3046.18 2567.96,3046.18 2601.76,3079.98 2601.76,3167.76 v1(2627,3193)
  Bottom Layer w8: v1(336.62,1582.23) J19.23@397.49,1582.23 ; R235.1@2626,3240.22 2626.5,3239.72 2626.5,3193.5 v1(2627,3193)
TRACE_DATA3: J19.25 R217.1 | length 4169.7
  SIG1 w6: v1(459.31,1601.92) 576.68,1601.92 595.76,1621 595.76,1696.98 595.76,1725.98 602.26,1732.48 625.77,1732.48 632.27,1738.98 632.27,1751.98 625.77,1758.48 598.02,1758.48 591.52,1764.98 591.52,1777.98 598.02,1784.48 637.27,1784.48 643.77,1790.98 643.77,1803.98 637.27,1810.48 615.3,1810.48 608.8,1816.98 608.8,1826.17 614.74,1832.11 739.53,1956.9 897.75,1956.9 900.75,1956.9 907.25,1963.4 907.25,1985.56 913.75,1992.06 926.75,1992.06 933.25,1985.56 933.25,1953.62 939.75,1947.12 952.75,1947.12 959.25,1953.62 959.25,1985.56 965.75,1992.06 978.75,1992.06 985.25,1985.56 985.25,1950.3 991.75,1943.8 1004.75,1943.8 1011.25,1950.3 1011.25,1985.56 1017.75,1992.06 1030.75,1992.06 1037.25,1985.56 1037.25,1950.3 1043.75,1943.8 1056.75,1943.8 1063.25,1950.3 1063.25,1985.56 1069.75,1992.06 1082.75,1992.06 1089.25,1985.56 1089.25,1950.3 1095.75,1943.8 1108.75,1943.8 1115.25,1950.3 1115.25,1985.56 1121.75,1992.06 1134.75,1992.06 1141.25,1985.56 1141.25,1950.3 1147.75,1943.8 1160.75,1943.8 1167.25,1950.3 1167.25,1950.4 1173.75,1956.9 1179.27,1956.9 1185.85,1956.9 1239.11,1903.64 v1(1643.87,1903.64)
  SIG2 w6: v1(1643.87,1903.64) 1643.87,1906.47 1941.69,2204.29 1941.69,2530.1 2007,2595.42 2007,2743.66 2309.72,3046.37 2436.86,3046.37 2448.66,3058.18 2523.18,3058.18 2586.57,3121.57 2586.57,3242.07 v1(2696.49,3351.99)
  Bottom Layer w8: J19.25@397.49,1601.92 v1@458.81,1601.92 ; R217.1@2613.94,3395.96 2613.94,3365.06 2627.01,3351.99 v1(2696.49,3351.99)
TRACE_DATA4: J19.27 R221.1 | length 3990.2
  SIG1 w6: v1(336.62,1621.6) 321.43,1621.6 313,1613.18 313,1566.78 343.88,1535.89 579.48,1535.89 639.7,1596.11 672.55,1628.95 672.55,1638.15 641.01,1669.69 641.01,1678.88 650.2,1688.07 659.39,1688.07 696.05,1651.41 705.24,1651.41 714.44,1660.6 714.44,1669.8 677.77,1706.46 677.77,1715.65 686.97,1724.84 696.16,1724.84 727.7,1693.3 736.89,1693.3 751,1707.41 751,1720.21 751,1753 756.74,1758.74 758.87,1760.87 758.87,1770.06 734.08,1794.85 734.08,1804.04 743.27,1813.23 752.46,1813.23 778.27,1787.43 787.46,1787.43 796.65,1796.62 796.65,1805.81 770.85,1831.62 770.85,1840.81 780.04,1850 789.23,1850 814.02,1825.21 823.21,1825.21 832.42,1834.42 845.47,1847.47 854.66,1847.47 861.16,1840.97 861.16,1808.25 867.66,1801.75 880.66,1801.75 887.16,1808.25 887.16,1848.16 893.66,1854.66 906.66,1854.66 913.16,1848.16 913.16,1808.25 919.66,1801.75 932.66,1801.75 939.16,1808.25 939.16,1848.16 945.66,1854.66 958.66,1854.66 965.16,1848.16 965.16,1808.25 971.66,1801.75 984.66,1801.75 991.16,1808.25 991.16,1844.89 997.66,1851.39 1000.66,1851.39 v1(1581,1851.39)
  SIG2 w6: v1(1581,1851.39) 1581,2213.55 1702.62,2335.17 1702.62,2474.6 1933.38,2705.37 1933.38,2983.41 2073.77,3123.8 2178.11,3123.8 v1(2178.67,3124.37)
  Bottom Layer w8: v1(336.62,1621.6) J19.27@397.49,1621.6 ; v1(2178.67,3124.37) 2294.53,3240.22 R221.1@2327.86,3240.22
TRACE_DATA5: J19.29 R228.1 | length 4115.6
  SIG1 w6: v1(459.31,1641.29) 481.38,1619.21 560.83,1619.21 572.62,1631 575.62,1634 575.62,1643.19 569.12,1649.69 536.71,1649.69 530.21,1656.19 530.21,1669.19 536.71,1675.69 577.26,1675.69 583.76,1682.19 583.76,1695.19 577.26,1701.69 536.71,1701.69 530.21,1708.19 530.21,1721.19 536.71,1727.69 573.01,1727.69 579.51,1734.19 579.51,1740.99 579.51,1823.21 714.98,1958.67 717.98,1961.67 717.98,2018.56 724.48,2025.06 737.48,2025.06 743.98,2018.56 743.98,1975.4 750.48,1968.9 763.48,1968.9 769.98,1975.4 769.98,2018.56 776.48,2025.06 789.48,2025.06 795.98,2018.56 795.98,1975.4 802.48,1968.9 815.48,1968.9 821.98,1975.4 821.98,2016.69 828.48,2023.19 841.48,2023.19 847.98,2016.69 847.98,1976.5 854.48,1970 865.52,1970 874.31,1970 902.16,1997.85 911.66,2007.35 911.66,2050.82 918.16,2057.32 931.16,2057.32 937.66,2050.82 937.66,2010.38 944.16,2003.88 957.16,2003.88 963.66,2010.38 963.66,2050.82 970.16,2057.32 983.16,2057.32 989.66,2050.82 989.66,2010.38 996.16,2003.88 1009.16,2003.88 1015.66,2010.38 1015.66,2050.82 1022.16,2057.32 1035.16,2057.32 1041.66,2050.82 1041.66,2010.38 1048.16,2003.88 1061.16,2003.88 1067.66,2010.38 1067.66,2050.82 1074.16,2057.32 1087.16,2057.32 1093.66,2050.82 1093.66,2010.56 1100.16,2004.06 1154.59,2004.06 1157.79,2004.06 1239.85,1922 1609.78,1922 v1(1633.53,1945.74)
  SIG2 w6: v1(1633.53,1945.74) 1917.69,2229.9 1917.69,2540.05 1983,2605.36 1983,2753.6 2299.77,3070.37 2426.92,3070.37 2498,3141.46 2498,3182.61 v1(2498.14,3182.74)
  Bottom Layer w8: J19.29@397.49,1641.29 v1@458.81,1641.29 ; v1(2498.14,3182.74) 2498.32,3182.92 2498.32,3240.04 R228.1@2498.5,3240.22
TRACE_DATA6: J19.31 R232.1 | length 4153.8
  SIG1 w6: v1(468.75,1680.66) 468.75,1810.75 519.47,1861.47 576.75,1918.75 585.94,1918.75 617.42,1887.27 626.61,1887.27 635.8,1896.46 635.8,1905.66 602.46,1938.99 602.46,1948.18 611.66,1957.38 620.85,1957.38 654.19,1924.04 663.38,1924.04 672.57,1933.23 672.57,1942.43 639.23,1975.76 639.23,1984.95 648.43,1994.15 657.62,1994.15 683,1968.77 692.19,1968.77 701.38,1977.96 701.38,1987.15 677.86,2010.67 677.86,2019.86 700.65,2042.65 732.4,2074.4 1106.89,2074.4 1241.29,1940 1593,1940 1616.74,1963.74 1658.86,1963.74 1726.6,1896 v1(1762,1896)
  SIG2 w6: v1(1762,1896) 1883.94,1896 2013.69,2025.74 2013.69,2337.99 2138,2462.31 2138,2641.53 2482.65,2986.18 2690.63,2986.18 2912,3207.55 v1(2912,3366.77)
  Bottom Layer w8: J19.31@397.49,1660.97 449.06,1660.97 v1(468.75,1680.66) ; v1(2912,3366.77) R232.1@2912,3387.3
TRACE_DATA7: J19.33 R236.1 | length 4208.4
  SIG1 w6: v1(336.62,1680.66) 404.66,1680.66 429,1705 429,1912.03 455.4,1938.42 475.9,1958.93 485.09,1958.93 520.29,1923.73 529.48,1923.73 538.67,1932.93 538.67,1942.12 500.65,1980.14 500.65,1989.33 509.85,1998.52 519.04,1998.52 554.15,1963.41 563.34,1963.41 572.53,1972.61 572.53,1981.8 540.25,2014.08 540.25,2023.27 576.8,2059.83 625.14,2108.17 1093.83,2108.17 1248,1954 1498.5,1954 1527.5,1983 1770,1983 v1(1807,1946)
  SIG2 w6: v1(1807,1946) 1900,1946 1989.69,2035.69 1989.69,2510.22 2084,2604.54 2084,2742.03 2340.34,2998.37 2460.9,2998.37 2472.71,3010.18 2642.5,3010.18 2776,3143.68 v1(2776,3366.77)
  Bottom Layer w8: v1(336.62,1680.66) J19.33@397.49,1680.66 ; v1(2776,3366.77) R236.1@2776,3387.3
TRD1_N: D18.1 L7.4 R260.1 R265.2 | length 203.2
  Bottom Layer w4.8: L7.4@1274.27,3589.95 1283.68,3580.54 1294.98,3580.54 1300.15,3575.36 1313.06,3575.36 1315.88,3578.17 1315.88,3584.37 1320.25,3588.75 D18.1@1322.29,3588.75 1324.32,3588.75 1328.7,3584.37 1328.7,3578.17 1331.51,3575.36 1354.29,3575.36 1384.27,3575.36 1387.08,3578.17 1387.08,3578.96 1394.53,3586.4 R265.2@1396.49,3586.4 1384.23,3598.67 1378.13,3598.67 R260.1@1358.29,3618.51
TRD1_P: D19.1 L7.1 R270.2 R274.2 | length 203.2
  Bottom Layer w4.8: L7.1@1274.27,3550.58 1283.68,3559.99 1294.98,3559.99 1300.15,3565.16 1313.06,3565.16 1315.88,3562.35 1315.88,3556.15 1320.25,3551.78 D19.1@1322.29,3551.78 1324.32,3551.78 1328.7,3556.15 1328.7,3562.35 1331.51,3565.16 1358.51,3565.16 1384.27,3565.16 1387.08,3562.35 1387.08,3561.57 1394.53,3554.12 R270.2@1396.49,3554.12 1384.23,3541.86 1378.13,3541.86 R274.2@1358.29,3522.02
TRD2_N: C157.2 L7.3 | length 121.1
  Bottom Layer w4.8: C157.2@1077.67,3615.54 1077.67,3578.17 1080.48,3575.36 1099.3,3575.36 1128.31,3575.36 1133.48,3580.54 1144.78,3580.54 L7.3@1154.19,3589.95
TRD2_P: C161.2 L7.2 | length 121.1
  Bottom Layer w4.8: C161.2@1077.67,3524.99 1077.67,3562.35 1080.48,3565.16 1103.52,3565.16 1128.31,3565.16 1133.48,3559.99 1144.78,3559.99 L7.2@1154.19,3550.58
TRD3_N: C157.1 D15.1 J4.2 L11.4 R281.2 | length 545.4
  Top Layer w4.8: R281.2@663.7,3615.44 682.96,3596.18 682.96,3585.19 691.13,3577.01 725.71,3577.01 754.4,3605.7 J4.2@758.25,3605.7
  Top Layer w30: J4.2@758.25,3605.7 769.88,3594.07 815.21,3594.07 L11.4@848.49,3627.35
  Bottom Layer w4.8: J4.2@758.25,3605.7 788.58,3575.36 859.34,3575.36 865.3,3581.32 865.3,3585.41 869.67,3589.78 D15.1@873.77,3589.78 877.25,3589.78 881.62,3585.41 881.62,3580.65 886.91,3575.36 927.69,3575.36 927.79,3575.46 948.5,3575.46 948.6,3575.36 994.86,3575.36 997.67,3578.17 C157.1@997.67,3615.54
TRD3_P: C161.1 D17.1 J4.1 L11.1 R275.2 | length 548.8
  Top Layer w4.8: R275.2@663.7,3525.09 682.96,3544.34 682.96,3556.72 693.05,3566.81 726.78,3566.81 758.25,3535.34 J4.1@758.25,3534.83
  Top Layer w30: J4.1@758.25,3534.83 769.88,3546.46 815.21,3546.46 L11.1@848.49,3513.18
  Bottom Layer w4.8: J4.1@758.25,3534.83 788.58,3565.16 859.34,3565.16 865.3,3559.21 865.3,3555.11 869.67,3550.74 D17.1@873.77,3550.74 877.86,3550.74 882.23,3555.11 882.23,3559.21 888.19,3565.16 931.91,3565.16 932.01,3565.26 944.27,3565.26 944.37,3565.16 994.86,3565.16 997.67,3562.35 C161.1@997.67,3524.99
TX0_N: J7.58 R366.1 | length 420.7
  Top Layer w4.8: J7.58@623.08,662.86 626.18,665.96 668.76,665.96 670.41,667.61 695.87,667.61 705.01,667.61 711.21,661.41 711.21,635.85 723.39,623.67 744.24,623.67 756.41,635.85 756.41,661.41 762.61,667.61 768,667.61 811.52,667.61 868.23,610.9 939.5,610.9 942.31,608.09 942.31,605.9 946.21,602 R366.1@947,602
TX0_P: J7.56 R365.1 | length 420.7
  Top Layer w4.8: J7.56@623.08,682.55 626.18,679.46 668.76,679.46 670.41,677.81 695.87,677.81 709.24,677.81 721.41,665.63 721.41,640.07 727.61,633.87 740.01,633.87 746.21,640.07 746.21,665.63 758.39,677.81 768,677.81 815.75,677.81 872.45,621.1 939.5,621.1 942.31,623.91 942.31,626.1 946.21,630 R365.1@947,630
TX1_N: J7.52 R364.1 | length 419.7
  Top Layer w4.8: J7.52@623.08,721.92 626.18,725.01 668.76,725.01 670.41,726.66 705.53,726.66 712.5,719.69 712.5,704.17 723.96,692.71 748.13,692.71 760.31,704.88 760.31,726.38 767.38,733.45 785.23,733.45 792,726.68 792,709.66 803.86,697.8 847.66,697.8 875.5,669.95 939.5,669.95 942.31,667.14 942.31,664.95 946.21,661.06 R364.1@947,661.06
TX1_P: J7.50 R363.1 | length 419.7
  Top Layer w4.8: J7.50@623.08,741.6 626.18,738.51 668.76,738.51 670.41,736.86 709.75,736.86 722.7,723.92 722.7,708.4 728.19,702.91 743.91,702.91 750.11,709.11 750.11,730.61 763.15,743.65 789.45,743.65 802.2,730.91 802.2,713.89 808.09,708 851.88,708 879.73,680.16 939.5,680.16 942.31,682.97 942.31,685.16 946.21,689.06 R363.1@947,689.06
TX2_CLK_N: J7.40 R167.1 R349.1 | length 711.2
  Top Layer w4.8: J7.40@623.08,840.03 626.18,843.12 668.76,843.12 670.41,844.77 708.06,844.77 717.59,844.77 725.49,836.87 v1(727,836.87) 728.51,836.87 736.41,844.77 747.31,844.77 754.27,837.8 754.27,822.28 765.74,810.82 789.91,810.82 802.09,822.99 802.09,845.14 808.86,851.91 826.93,851.91 833.78,845.07 833.78,812.85 847.02,799.61 867.78,799.61 881.2,813.03 881.2,836.59 889.38,844.77 895.92,844.77 898.73,841.96 898.73,839.77 902.63,835.87 R349.1@903.42,835.87
  SIG1 w4.8: v1(727,836.87) 729.41,836.87 736.41,843.87 789.49,843.87 803.38,857.76 803.38,926.99 813.38,937 878.63,937 881.45,934.19 v1(881.45,914.49)
  Bottom Layer w4.8: v1(881.45,914.49) 883.05,916.09 883.05,926.19 885.86,929 R167.1@903.42,929
TX2_CLK_P: J7.38 R164.1 R345.1 | length 710.8
  Top Layer w4.8: J7.38@623.08,859.71 626.18,856.62 668.76,856.62 670.41,854.97 703.84,854.97 717.59,854.97 725.49,862.87 v1(727,862.87) 728.51,862.87 736.41,854.97 751.53,854.97 764.47,842.03 764.47,826.51 769.96,821.02 785.68,821.02 791.89,827.22 791.89,849.37 804.63,862.11 831.16,862.11 843.98,849.29 843.98,817.08 851.25,809.81 863.55,809.81 871,817.25 871,840.82 885.15,854.97 895.92,854.97 898.73,857.78 898.73,859.18 R345.1@903.42,863.87
  SIG1 w4.8: v1(727,862.87) 729.41,862.87 736.41,855.87 784.52,855.87 791.38,862.73 791.38,931.96 808.41,949 878.63,949 881.45,951.81 v1(881.45,971.51)
  Bottom Layer w4.8: v1(881.45,971.51) 883.05,969.91 883.05,959.81 885.86,957 R164.1@903.42,957
TX3_N: J7.34 R135.1 R341.1 | length 783.1
  Top Layer w4.8: J7.34@623.08,899.08 626.18,902.18 668.76,902.18 670.41,903.83 697.59,903.83 705.49,895.93 v1(707,895.93) 708.51,895.93 716.41,903.83 755.86,903.83 779.91,927.88 779.91,955.97 786.44,962.5 798.1,962.5 805,955.6 805,908.29 818.24,895.04 837.64,895.04 850.88,908.28 850.88,929.31 859.46,937.9 895.92,937.9 898.73,935.09 898.73,932.9 902.63,929 R341.1@903.42,929
  SIG2 w4.8: v1(707,895.93) 709.41,895.93 716.41,902.93 729.91,902.93 890.84,742 923.08,742 925.89,739.19 v1(925.89,716.68)
  Bottom Layer w4.8: v1(925.89,716.68) 925.89,740.09 928.7,742.9 939.5,742.9 942.31,740.09 942.31,737.9 946.21,734 R135.1@947,734
TX3_P: J7.32 R51.1 R327.1 | length 783.1
  Top Layer w4.8: J7.32@623.08,918.77 626.18,915.68 668.76,915.68 670.41,914.03 697.59,914.03 705.49,921.93 v1(707,921.93) 708.51,921.93 716.41,914.03 751.64,914.03 769.71,932.1 769.71,960.19 782.22,972.7 802.33,972.7 815.2,959.82 815.2,912.51 822.47,905.24 833.41,905.24 840.67,912.51 840.67,933.54 855.24,948.1 895.92,948.1 898.73,950.91 898.73,953.1 902.63,957 R327.1@903.42,957
  SIG2 w4.8: v1(707,921.93) 709.41,921.93 716.41,914.93 734.89,914.93 895.81,754 923.08,754 925.89,756.81 v1(925.89,779.32)
  Bottom Layer w4.8: v1(925.89,779.32) 925.89,755.91 928.7,753.1 939.5,753.1 942.31,755.91 942.31,758.1 946.21,762 R51.1@947,762
TX4_N: J7.46 R160.1 R361.1 | length 752.2
  Top Layer w4.8: J7.46@623.08,780.97 626.18,784.07 668.76,784.07 670.41,785.72 697.59,785.72 705.49,777.82 v1(707,777.82) 708.51,777.82 716.41,785.72 802.2,785.72 818,769.91 818,741.36 832.48,726.89 857.47,726.89 871.01,740.43 871.01,764.96 873.82,767.78 883.95,767.78 908.82,742.9 939.5,742.9 942.31,740.09 942.31,737.9 946.21,734 R361.1@947,734
  SIG1 w4.8: v1(707,777.82) 709.41,777.82 716.41,784.82 797.96,784.82 821.61,808.46 821.61,826.62 841.74,846.75 937.01,846.75 950,833.76 v1(950,813.72)
  Bottom Layer w4.8: R160.1@925.52,813.77 949.95,813.77 v1(950,813.72)
TX4_P: J7.44 R138.1 R351.1 | length 751.5
  Top Layer w4.8: J7.44@623.08,800.66 626.18,797.57 668.76,797.57 670.41,795.92 697.59,795.92 705.49,803.82 v1(707,803.82) 708.51,803.82 716.41,795.92 806.42,795.92 828.2,774.14 828.2,745.59 836.7,737.09 853.24,737.09 860.81,744.65 860.81,769.19 869.6,777.97 888.17,777.97 913.05,753.1 939.5,753.1 942.31,755.91 942.31,758.1 946.21,762 R351.1@947,762
  SIG1 w4.8: v1(707,803.82) 709.41,803.82 716.41,796.82 792.99,796.82 809.61,813.43 809.61,831.59 836.77,858.75 943.52,858.75 951.68,866.91 951.68,884.13 v1(950,885.81)
  Bottom Layer w4.8: R138.1@925.46,885.92 925.52,885.86 949.95,885.86 v1(950,885.81)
